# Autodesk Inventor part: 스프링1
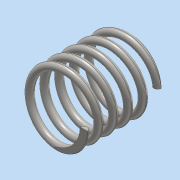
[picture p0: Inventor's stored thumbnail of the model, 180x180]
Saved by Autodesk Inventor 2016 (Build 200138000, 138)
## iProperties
Created: 2019-11
Part Number: 스프링1
Material: 스테인레스 스틸
Document SubType Name: Modeling
Designer: user
Density: 8 g/cm^3
Appearance: 반연마
Mass: 6.57302 g
Surface Area: 16.7216 cm^2
Volume: 0.821628 cm^3
Author: user
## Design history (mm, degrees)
sketch "스케치1"
  geometry: L1 (0, 0)-(8.5, 0); L2 (8.5, 0)-(8.5, -20.5); L3 (8.5, -20.5)-(0, -20.5); L4 (0, -20.5)-(0, 0); C1 r 1 at (8.5, 0)
  constraints: 8 end point, 2 parallel, 1 centre point, 1 coincident, 1 horizontal, 1 perpendicular
  dimensions: "d0" = 17 diameter of L2 L4; "d1" = 20.5 distance between parallel lines of L1 L3 (derived); "d2" = 2 diameter of C1
feature "코일1" sketch "스케치1" pitch "d3" = 10; turns "d5" = 5; dims "d4" = 20.5 (= d1), "d6" = 0, angle "d7" = 90 deg, angle "d8" = 90 deg, "d9" = 0, "d10" = 0
sketch "스케치2"
  geometry: L1 (-20, 0)-(20, 0); L2 (20, 0)-(20, -20.5); L3 (20, -20.5)-(-20, -20.5); L4 (-20, -20.5)-(-20, 0); 2 further points
  constraints: 8 end point, 2 parallel, 1 coincident, 1 horizontal, 1 midpoint, 1 perpendicular
  dimensions: "d11" = 40 distance between parallel lines of L2 L4; "d15" = 20.5 distance between parallel lines of L1 L3 (= d1)
extrude "돌출2" sketch "스케치2" stored distance "d16" = 28.25; taper "d17" = 0 deg
node "솔리드1"
